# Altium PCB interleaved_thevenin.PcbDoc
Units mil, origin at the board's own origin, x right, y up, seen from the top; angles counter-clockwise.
Board outline 3900.03 x 2830.03 mil, 2 copper layers (Top Layer, Bottom Layer); 43 components, 29 nets, 149 pads, 13 vias.
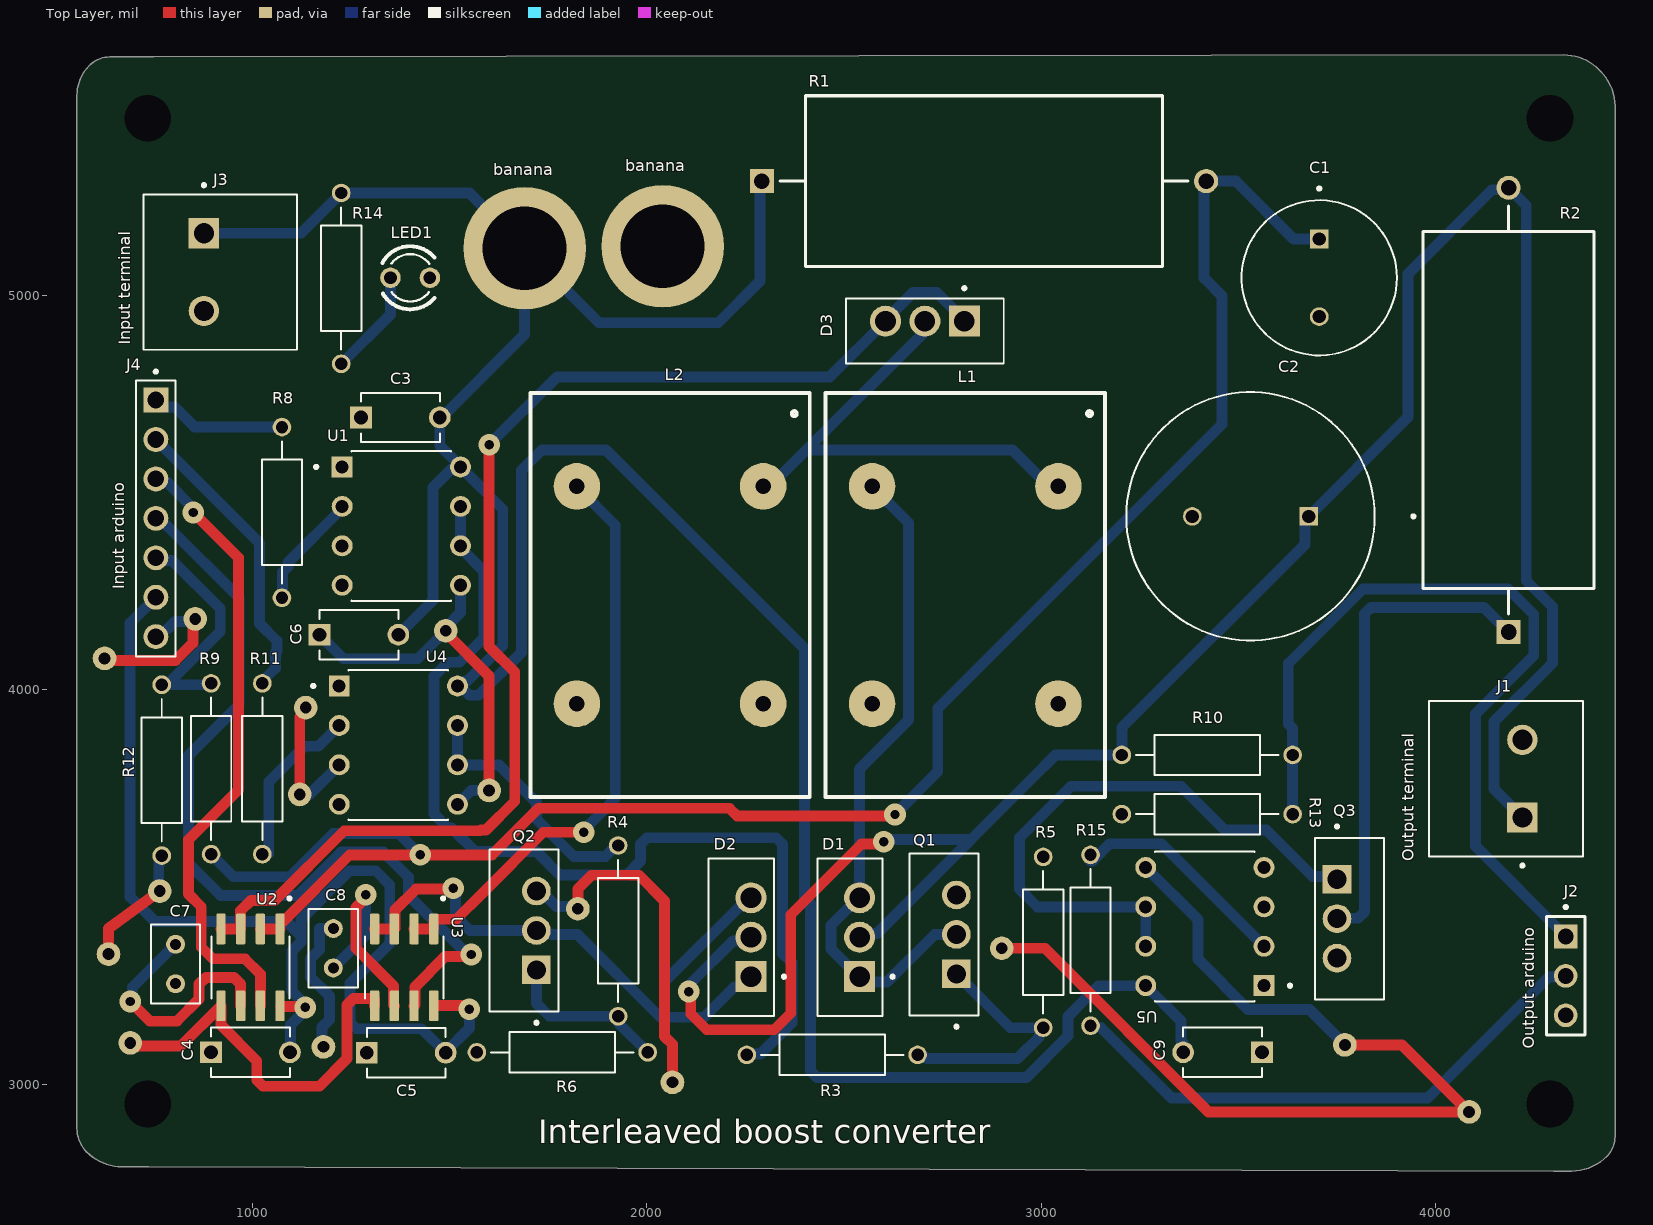
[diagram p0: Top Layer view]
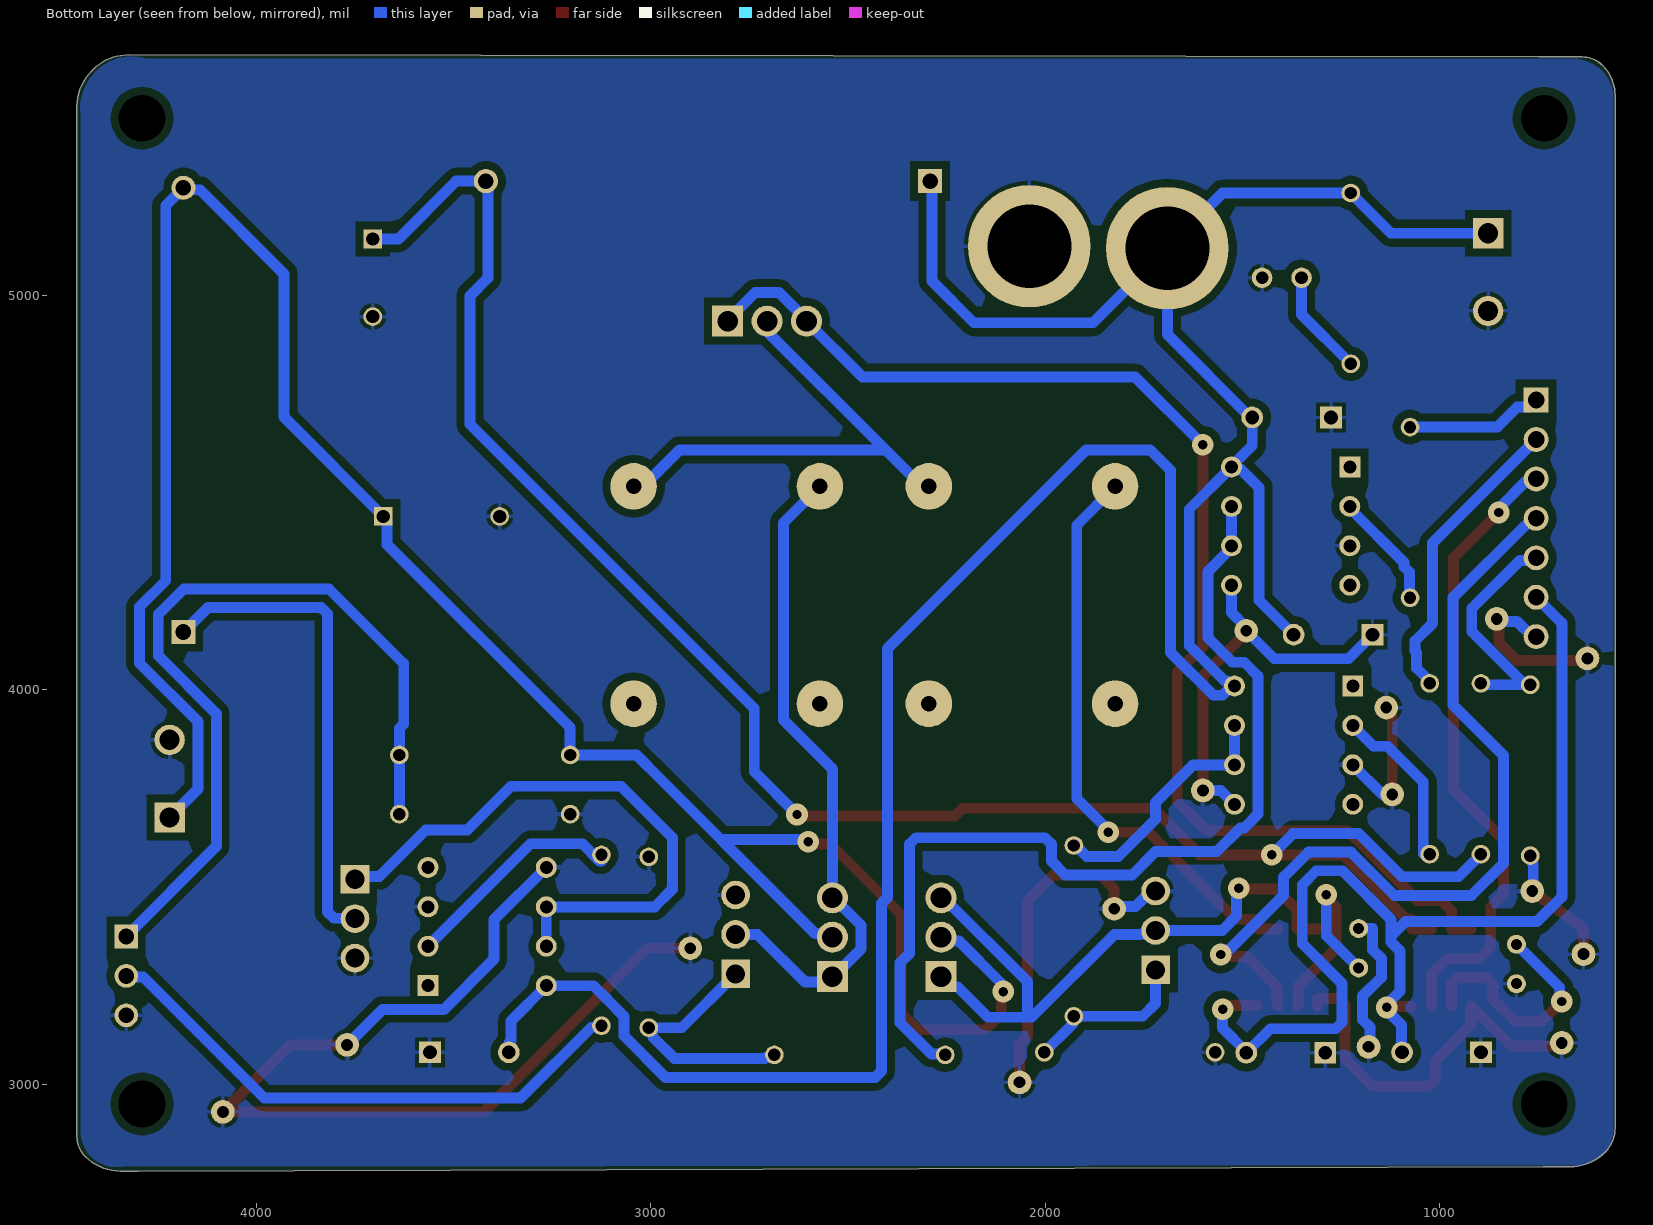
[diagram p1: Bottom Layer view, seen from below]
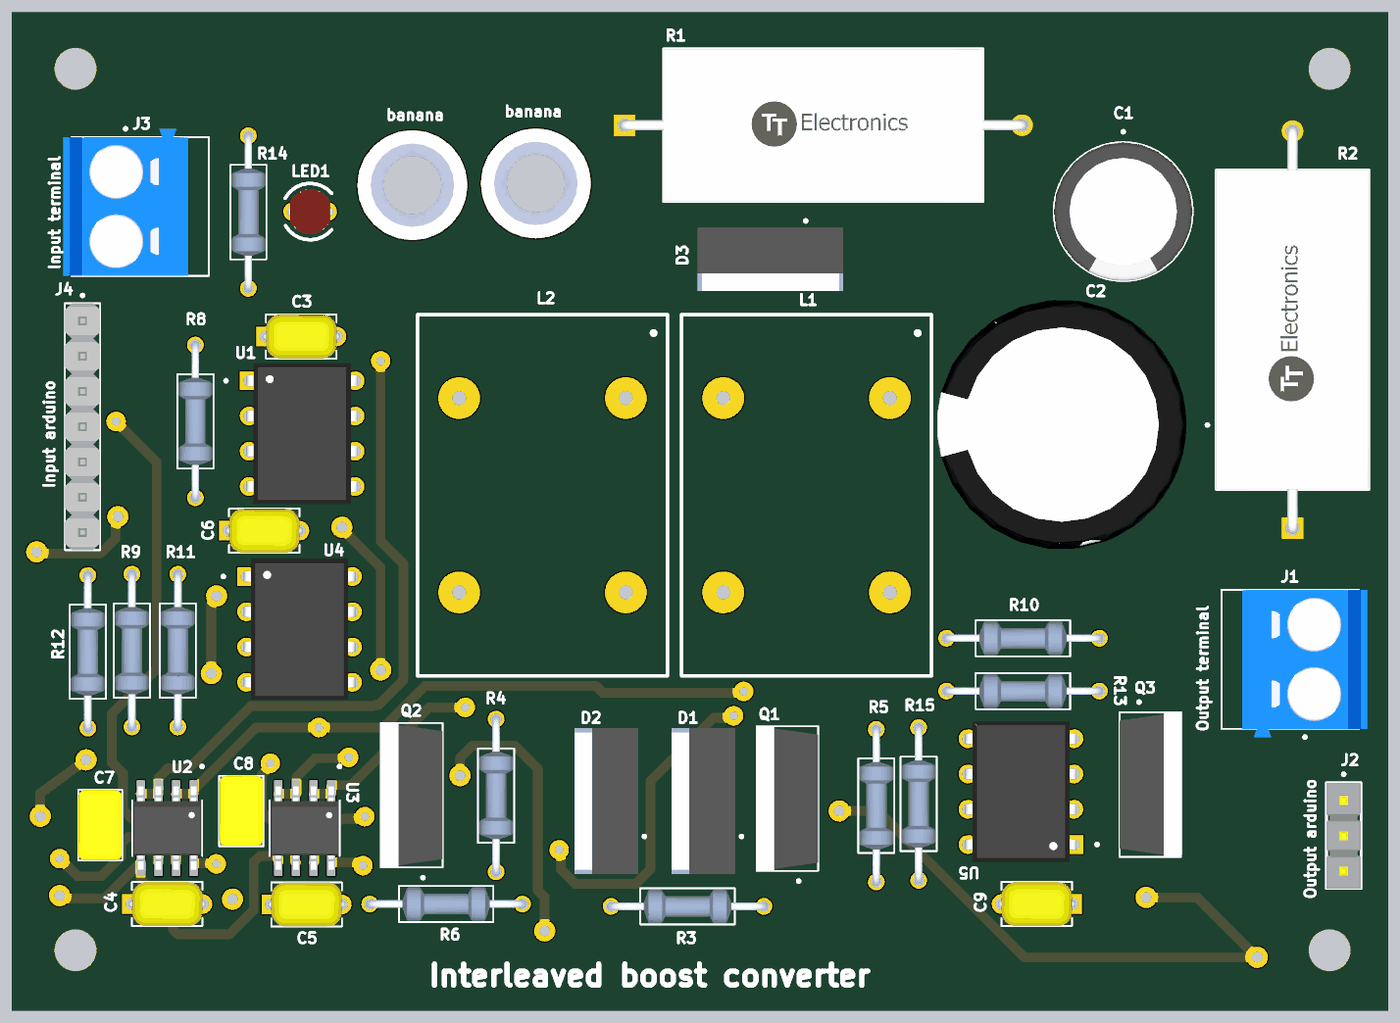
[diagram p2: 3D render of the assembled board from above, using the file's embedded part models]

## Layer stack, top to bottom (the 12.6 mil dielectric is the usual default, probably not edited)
Top Solder: solder mask 0.4, Solder Resist, Dk 3.5
Top Layer: signal copper 1.4
Dielectric 1: dielectric 12.6, FR-4, Dk 4.8
Bottom Layer: signal copper 1.4
Bottom Solder: solder mask 0.4, Solder Resist, Dk 3.5

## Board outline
580.05,2827.86 cw(c640.56,2888.37) 554.99,2888.37 554.99,2910 554.98,5456.69 554.98,5507.57 cw(c662.43,5507.57) 586.45,5583.55 cw(c638.3,5531.7) 638.3,5605.02 749.99,5605.02 4324.99,5610.02 cw(c4325,5484.28) 4413.9,5573.19 4418.19,5568.9 cw(c4329.29,5480) 4455.02,5480 4455.01,2950 4455.01,2867.78 cw(c4382.93,2867.78) 4433.9,2816.81 cw(c4345,2905.71) 4345,2779.99 4299.98,2779.99 736.48,2791.03 725,2791.03 690,2791.03 668.95,2791.03 cw(c668.95,2916.76)

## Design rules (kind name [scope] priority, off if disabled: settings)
Clearance [All] p1: gap=19.68 ignorepadtopadclearanceinfootprint=FALSE
HoleSize [All] p1: absolutevalues=TRUE maxlimit=300 minlimit=1 maxpercent=80.000 minpercent=20.000
PolygonConnect [All] p1: connectstyle=Relief reliefconductorwidth=10 reliefentries=4 polygonreliefangle="90 Angle" airgapwidth=10
RoutingVias [All] p1: holewidth=23.62 width=55.12 viastyle="Through Hole" minholewidth=23.62 minwidth=55.12 maxholewidth=39.37 maxwidth=78.74
SilkToSolderMaskClearance [IsPad] p1: minsilkscreentomaskgap=6 clearancetoexposedcopper=TRUE
SolderMaskExpansion [All] p1: expansion=4 istentingtop=FALSE
SupplyNets "Schematic Supply Nets_2" [InNet('+12')] p1: voltage=0.000
SupplyNets "Schematic Supply Nets_1" [InNet('GND')] p2: voltage=0.000
SupplyNets "Schematic Supply Nets" [InNet('+5')] p3: voltage=0.000
Width [All] p1: maxlimit=393.7 minlimit=27.56 preferedwidth=27.56 minimp=50.000000 maximp=50.000000 favimp=50.000000
28 further rules are at their usual default settings.

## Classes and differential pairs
component class Sheet1: C1 C2 C3 C4 C5 C6 C7 C8 C9 D1 D2 J1 J2 J3 J4 L1 L2 LED1 Q1 Q2 Q3 R1 R2 R3 R4 R5 R6 R8 R9 R10 R11 R12 R13 R14 R15 U1 U2 U3 U4 U5

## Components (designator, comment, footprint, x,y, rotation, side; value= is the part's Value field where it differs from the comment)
1 "Banana con" KEYSTONE_575-4 2040,5125 r90 top
C1 "470uF" 470uF 3705,5045 r270 top
C2 "2200uF cap" "2200uF cap" 3530.65,4440 r180 top
C3 "ceramic cap 100nF" "ceramic cap 100nF" 1375,4690.81 r0 top
C4 "ceramic cap 100nF" "ceramic cap 100nF" 995,3081.1 r0 top
C5 "ceramic cap 100nF" "ceramic cap 100nF" 1390,3080 r0 top
C6 "ceramic cap 100nF" "ceramic cap 100nF" 1270,4140 r0 top
C7 "1nF ceramic cap" "1nF ceramic cap" 805,3305 r270 top
C8 "1nF ceramic cap" "1nF ceramic cap" 1205,3345 r90 top
C9 "ceramic cap 100nF" "ceramic cap 100nF" 3460,3081.1 r180 top
D1 "MBR20100CT" TO254P1066X482X2286-3 2514.88,3372.89 r90 top
D2 "MBR20100CT" TO254P1066X482X2286-3 2239.4,3372.89 r90 top
D3 "MBR20100CT" TO254P1066X482X2286-3 2705,4910.31 r180 top
J1 "output" "terminal block" 4220,3775 r90 top
J2 "output arduino" "3 male pins header" 4330,3275 r90 top
J3 "input power" "terminal block" 876.8,5059.36 r270 top
J4 "input arduino" "7 male pin header" 755,4435 r270 top
L1 "WE-HIDA_1715" "2mH inductor" 2807.45,4240.59 r270 top
L2 "WE-HIDA_1715" "2mH inductor" 2058.78,4240.59 r270 top
LED1 "Red LED" "Red LED" 1400,5045 r0 top
Q1 "IRF540NPBF" TO254P1054X469X1930-3 2753.09,3380 r90 top
Q2 "IRF540NPBF" TO254P1054X469X1930-3 1688.09,3390 r90 top
Q3 "IRF540NPBF" TO254P1054X469X1930-3 3781.91,3420 r270 top
R1 "6.8ohm" "5W power resistor" 2855,5290 r0 top
R2 "47ohm" "5W power resistor" 4185,4710 r90 top
R3 "22ohm" "TH resistor" 2470,3074.58 r0 top
R4 "22ohm" "TH resistor" 1927.25,3388.95 r270 top
R5 "10k ohm" "TH resistor" 3005,3360 r270 top
R6 "10kohm" "TH resistor" 1785.69,3081.1 r0 top
R8 "330 ohm" "TH resistor" 1074.82,4450 r270 top
R9 "10kohm" "TH resistor" 895,3800 r270 top
R10 "330kohm" "TH resistor" 3420.95,3835 r180 top
R11 "330 ohm" "TH resistor" 1025,3800 r270 top
R12 "1kohm" "TH resistor" 770,3796.54 r90 top
R13 "65kohm" "TH resistor" 3420.95,3685 r0 top
R14 "560ohm" "TH resistor" 1225,5043.46 r90 top
R15 "330 ohm" "TH resistor" 3125,3365 r90 top
U1 "TLP250" DIP762W50P254L966H485Q8 1377.47,4415.4 r0 top
U2 "ACS712" ACS712 995,3296.34 r270 top
U3 "ACS712" ACS712 1384.81,3296.34 r270 top
U4 "TLP250" DIP762W50P254L966H485Q8 1370,3860 r0 top
U5 "TLP250" DIP762W50P254L966H485Q8 3415,3400 r180 top
? "Banana con" KEYSTONE_575-4 1690,5120 r0 top

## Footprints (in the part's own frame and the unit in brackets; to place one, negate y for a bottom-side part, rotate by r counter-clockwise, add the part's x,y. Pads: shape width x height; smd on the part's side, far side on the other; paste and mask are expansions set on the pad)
"1nF ceramic cap" [mm]
  round 1.218 hole 0.71: 1(-1.27,0) 2(1.27,0)
  silkscreen extent -2.54,-1.59 2.54,1.59, body extent -2.54,-1.59 2.54,1.59, height 5.08
"2mH inductor" [mm]
  round 3 hole 1: 1(-7,6) 2(-7,-6) 3(7,-6) 4(7,6)
  silkscreen extent -13,-9 13,9
"3 male pins header" [mm]
  rect 1.53x1.53 / inner round 1.53 / far side rect 1.53x1.53 hole 1.02: 01(2.54,0)
  round 1.53 hole 1.02: 02(0,0) 03(-2.54,0)
  silkscreen extent -3.81,-1.24 4.53,1.24, body extent -3.81,-1.24 3.81,1.24, height 8.38
"5W power resistor" [mm]
  rect 1.55x1.55 hole 1 paste-2539.97 mask+0: 1(-14.305,0)
  round 1.55 hole 1 paste-2539.97 mask+0: 2(14.305,0)
  silkscreen extent -13.13,-5.5 13.13,5.5, body extent -15.18,-5.6 15.18,5.6, height 0.25
"7 male pin header" [mm]
  rect 1.605x1.605 / inner round 1.605 / far side rect 1.605x1.605 hole 1.07: 1(-7.62,0)
  round 1.605 hole 1.07: 2(-5.08,0) 3(-2.54,0) 4(0,0) 5(2.54,0) 6(5.08,0) 7(7.62,0)
  silkscreen extent -9.55,-1.27 8.89,1.27, body extent -8.89,-1.27 8.89,1.27, height 8.34
470uF [mm]
  round 1.2 hole 0.85: N(2.5,0)
  rect 1.2x1.2 hole 0.85: P(-2.5,0)
  silkscreen extent -5.85,-5 5,5, body extent -5,-5 5,5, height 12.5
"2200uF cap" [mm]
  round 1.2 hole 0.85: N(3.75,0)
  rect 1.2x1.2 hole 0.85: P(-3.75,0)
  silkscreen extent -10.59,-8 8,8, body extent -8.99,-9.02 8.99,8.97, height 3
ACS712 [mm]
  rrect25% 1.97x0.6 smd paste+0 mask+0.102: 1(-2.475,1.905) 2(-2.475,0.635) 3(-2.475,-0.635) 4(-2.475,-1.905) 5(2.475,-1.905) 6(2.475,-0.635) 7(2.475,0.635) 8(2.475,1.905)
  silkscreen extent -4.54,-2.52 2,2.6, body extent -3,-2.45 3,2.45, height 1.75
"ceramic cap 100nF" [mm]
  rect 1.398x1.398 / inner round 1.398 / far side rect 1.398x1.398 hole 0.89: 1(-2.54,0)
  round 1.398 hole 0.89: 2(2.54,0)
  silkscreen extent -2.54,-1.59 2.54,1.59, body extent -2.79,-1.59 2.79,1.59, height 5.86
DIP762W50P254L966H485Q8 [mm]
  rect 1.348x1.348 / inner round 1.348 / far side rect 1.348x1.348 hole 0.84: 1(-3.81,3.81)
  round 1.348 hole 0.84: 2(-3.81,1.27) 3(-3.81,-1.27) 4(-3.81,-3.81) 5(3.81,-3.81) 6(3.81,-1.27) 7(3.81,1.27) 8(3.81,3.81)
  silkscreen extent -5.58,-4.83 3.2,4.83, body extent -4.02,-5.09 4.02,5.09, height 4.51
KEYSTONE_575-4 [mm]
  round 7.9 hole 5.4: 1(0,0)
  body extent -3.96,-3.96 3.96,3.96, height 2.36
"Red LED" [mil]
  round 52 hole 32: A(-50,0) K(50,0)
  silkscreen extent -71,-80 61,80, body extent -60,-62 60,62, height 240
"terminal block" [mm]
  rect 1.95x1.95 / inner round 1.95 / far side rect 1.95x1.95 hole 1.3: 1(-2.5,0)
  round 1.95 hole 1.3: 2(2.5,0)
  silkscreen extent -5.7,-3.9 5,6, body extent -5.6,-4.5 5,4.5, height 12.6
"TH resistor" [mm]
  round 1.2 hole 0.8: 1(-5.5,0) 2(5.5,0)
  silkscreen extent -4.58,-1.3 4.58,1.3, body extent -5.77,-1.2 5.77,1.2, height 2.4
TO254P1054X469X1930-3 [mm]
  rect 1.845x1.845 / inner round 1.845 / far side rect 1.845x1.845 hole 1.23: 1(-2.54,-0.81)
  round 1.845 hole 1.23: 2(0,-0.81) 3(2.54,-0.81)
  silkscreen extent -6.04,-2.22 5.21,2.22, body extent -5.21,-2.22 5.21,2.22, height 19.3
TO254P1066X482X2286-3 [mm]
  rect 2x2 / inner round 2 / far side rect 2x2 hole 1.33: 1(-2.54,-0.627)
  round 2 hole 1.33: 2(0,-0.627) 3(2.54,-0.627)
  silkscreen extent -5.08,-2.85 5.08,2.09, body extent -5.25,-2.29 5.25,2.3, height 20.2

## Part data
1 ?: "Battery Holders, Contacts and Clips JACK", Package=None
C1: "470ÂµF 25V Aluminum Electrolytic Capacitors Radial, Can 2000 Hrs @ 105Â°C", Package="RADIAL-2 Panasonic"
C2: "CAP ALUM 2200UF 20% 35V RADIAL", Package="RADIAL-2 Panasonic"
C3 C4 C5 C6 C9: "AR 100nF Ceramic Multilayer Cap,50V dc,+125C,X7R Dielectric,+/-10%,Through Hole", Package="Radial AVX"
C7 C8: "SR Series 5.08 x 5.08 mm 1 nF 100 V Â±5% Tolerance C0G/NP0 Radial Lead/SkyCapÂ®", Package="Radial AVX / Kyocera"
D1 D2 D3: "20A, 100V, Planar Schottky", Package="TO-220AB-3 Taiwan Semiconductor"
J1 J3: library part "terminal block", Package=None
J2: library part "3 male pins header", Package=None
J4: library part "7 male pin header", Package=None
L1 L2: library part "2mH E shape"
LED1: "Red 619nm LED Indication - Discrete 1.9V Radial", Package=None
Q1 Q2 Q3: "RoHS Compliant", Package="TO-220 Infineon"
R1 R2: library part "5W power resistor", "CAW54R70JLF Thick Film Resistors - Through Hole 4.7 OHM 5% 5W", Ambient Temperature Range High=155°C, Case/Package=Axial, Power Rating=5W, Resistance=4.7Ω, Temperature Coefficient=400ppm/°C, Tolerance=5%, Voltage Rating=350V
R3 R4 R5 R6 R8 R9 R10 R11 R12 R13 R14 R15: library part "TH resistor", "1.07 kOhms Â±1% 0.25W, 1/4W Through Hole Resistor Axial - Metal Film", Package="RADIAL-2 YAGEO"
U1 U4 U5: "Logic Output Optoisolator - Push-Pull, Totem Pole 3750Vrms 1 Channel 40kV/Âµs CMTI 8-SMD", Package="DIP-8 Toshiba"
U2 U3: "Fully Integrated, Hall-Effect-Based Linear Current Sensor IC with 2.4 kVRMS Isolation and a Low-Resistance Current Conductor", Package=None

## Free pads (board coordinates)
  round 0 hole 118.11: 2(735,2950) 2(735,5450) 2(4290,2950) 2(4290,5450)
  round 60 hole 30: 5(690,3105) 9(855,4180) 11(625,4080) 12(1490,4150) 16(1135,3955) 18(1120,3735) 21(1825,3445) 22(2065,3005) 23(1180,3095) 24(765,3490) 25(635,3330) 26(4085,2930) 27(3770,3100) 28(2900,3345) GND(1600,3745)

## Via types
v1: diameter 55.12, hole 23.62, Top Layer to Bottom Layer, 13 vias

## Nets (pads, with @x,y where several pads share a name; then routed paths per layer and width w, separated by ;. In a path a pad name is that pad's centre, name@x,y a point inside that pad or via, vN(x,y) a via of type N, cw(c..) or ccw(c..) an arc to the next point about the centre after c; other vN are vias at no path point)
+5: C4.2 C5.2 J4.6 U2.8 U3.8 | length 2888.7
  Top Layer w27.56: U2.8@1071.97,3196.95 1132.02,3196.95 v1(1133.98,3195) ; C4.2 C4.2@1095,3088.53 ; U3.8@1461.78,3199.45 1533.09,3199.45 1542.54,3190 v1(1550,3190)
  Bottom Layer w27.56: J4.6 689.94,4169.94 689.94,3475.06 752.56,3412.44 1086.06,3412.44 1120,3378.5 ; C4.2 1096.39,3082.49 1096.39,3149.96 1137.07,3190.64 v1@1137.07,3198.1 ; v1(1133.98,3195) 1133.98,3202.46 1100.31,3236.12 1100.31,3338.36 1122.76,3360.8 1122.76,3378.5 1122.76,3417.76 1246.33,3541.33 1312.5,3541.33 1348.25,3505.58 1348.25,3357.02 1247.01,3255.77 1247.01,3157.13 1263.15,3140.98 1429.02,3140.98 C5.2 ; C5.2@1490,3082.68 1550,3142.68 v1(1550,3190)
+12: ?.1 C3.2 C6.2 C9.2 J3.1 R1.1 R14.2 U1.8 U4.8 U5.8 | length 7568.4
  Bottom Layer w27.56: J3.1 1122.79,5157.79 R14.2 1550,5260 ?.1 ; C6.2 1457.42,4227.42 1457.42,4513.39 1504.55,4560.52 1521.03,4560.52 1527.47,4566.97 1475,4619.44 C3.2 1479.97,4690.81 1690,4900.83 ?.1 ; U4.8 1526.9,4010 1539.66,4022.76 1544.57,4022.76 1634.71,4112.9 1634.71,4458.16 1532.45,4560.43 U1.8@1527.47,4560.43 ; U4.8@1530,4006.9 1550.6,3986.3 1573.5,3986.3 1681.96,4094.77 1681.96,4556.96 1733.7,4608.7 1896.3,4608.7 2400,4105 2400,3473.61 2415,3458.61 2415,3033.63 2431.14,3017.49 2962.49,3017.49 3067.91,3122.91 3067.91,3172.11 3110,3214.2 3110,3215 3145,3250 U5.8 3354.74,3160.26 3354.74,3110.26 C9.2@3360,3105 ; R1.1 2286.81,5285 2286.81,5036.81 2181.02,4931.02 1878.98,4931.02 ?.1
GND: 1.1 C1.N C2.N C3.1 C4.1 C5.1 C6.1 C7.2 C8.2 C9.1 J1.2 J2.03 J3.2 J4.7 LED1.K pad.5 pad.9 pad.11 pad.12 pad.16 pad.18 pad.21 pad.22 pad.23 pad.24 pad.25 pad.26 pad.27 pad.28 pad.GND Q1.3 Q2.3 Q3.3 R5.1 R6.1 R12.1 R13.1 U1.3 U1.5 U2.5 U3.5 U4.3 U4.5 U5.3 U5.5 | length 6903.1
  Top Layer w27.56: pad.25 635,3395 pad.24 ; pad.11@639.72,4075 805,4075 848.79,4118.79 848.79,4173.79 pad.9 ; pad.5 697.79,3097.21 818.31,3097.21 U2.5 920,3150 1010.71,3059.29 1010.71,3011.14 1026.85,2995 1170,2995 1240,3065 1240,3201.42 1256.14,3217.56 1307.84,3217.56 1309.81,3215.59 U3.5 ; pad.18 1120,3931.22 1135,3946.22 pad.16 ; pad.12 1490,4145.32 1600,4035.32 pad.GND ; pad.21 1825,3495 1860,3530 1980,3530 2045,3465 2045,3121.5 2065,3101.5 pad.22 ; pad.28 3009.2,3345 3424.2,2930 pad.26 3915,3100 pad.27
  Bottom Layer w27.56: J4.7 764.64,4135 803.43,4173.79 848.79,4173.79 pad.9 ; pad.24 762.28,3492.72 762.28,3558.37 766.23,3562.31 766.23,3576.23 R12.1 ; pad.18 1145,3735 U4.3 ; C6.1 1230.98,4079.02 1419.02,4079.02 pad.12 1490,4158.78 1527.47,4196.25 U1.5 ; pad.23 1176.21,3098.79 1176.21,3144.91 1195,3163.7 1195,3223.77 1147.56,3271.21 1147.56,3318.79 1170,3341.23 1170,3395 C8.2 ; U4.5 1554.62,3744.62 1599.62,3744.62 pad.GND ; Q2.3 1732.2,3490 1770.99,3451.21 1818.79,3451.21 pad.21 ; U5.5 3397.24,3417.76 3397.24,3317.36 3524.6,3190 3680,3190 pad.27
hycontrol: J2.02 R15.1 | length 1409.5
  Bottom Layer w27.56: R15.1 3128.77,3144.7 3150.3,3144.7 3330.08,2964.92 3979.92,2964.92 4287.03,3272.03 4327.03,3272.03 J2.02
"i/p voltage": J4.5 R9.1 R12.2 | length 569.5
  Bottom Layer w27.56: J4.5 761.64,4328.36 796.39,4328.36 918.46,4206.29 918.46,4148.46 792.91,4022.91 ; R12.2@779.09,4013.07 891.54,4013.07 R9.1
IP+_1: C1.P R1.2 R9.2 U2.1 U2.2 | length 4677.9
  Top Layer w27.56: U2.2 U2.1 ; U2.1@1071.97,3418.78 1077.88,3412.88 1246.83,3581.83 v1(1425.12,3581.83) 1607.07,3581.83 1725.25,3700 2209.14,3700 2229.14,3680 2625,3680 v1(2629.14,3684.14)
  Bottom Layer w27.56: R9.2 952.09,3526.38 1095.32,3526.38 1204.76,3635.82 1371.13,3635.82 v1(1425.12,3581.83) ; v1(2629.14,3684.14) 2737.76,3792.76 2737.76,3952.54 3458.67,4673.46 3458.67,4999.12 3413.19,5044.61 3413.19,5285 R1.2 3493.46,5290 3640.04,5143.43 C1.P
IP+_2: L2.2 U3.1 U3.2 | length 1494.6
  Top Layer w27.56: U3.2 U3.1 1459.81,3416.46 1461.78,3418.43 1516.9,3418.43 1585.17,3486.7 1737.45,3638.98 v1(1840,3638.98)
  Bottom Layer w27.56: L2.2@1822.56,4515 1920,4417.56 1920,3725 1840,3645 v1(1840,3638.98)
IP-_1: D3.1 D3.3 U2.3 U2.4 | length 3235.5
  Top Layer w27.56: U2.4 U2.3 970,3439.97 996.06,3466.03 1056.03,3466.03 1232.85,3642.85 1577.85,3642.85 1580,3645 1592.29,3645 1665,3717.71 1665,4045 1600.09,4109.91 v1@1600.09,4621.44
  Bottom Layer w27.56: v1(1600.09,4621.45) 1772.11,4793.47 2463.47,4793.47 D3.3 2605,4938 2674.83,5007.83 2735.17,5007.83 2779.41,4963.59 2779.41,4960.59 D3.1
IP-_2: D2.1 D2.3 Q2.2 U3.3 U3.4 | length 1635.8
  Top Layer w27.56: U3.4 U3.3 1361.78,3395.75 1361.78,3441.94 1414.57,3494.73 1506.9,3494.73 v1(1509.29,3497.12)
  Bottom Layer w27.56: v1@1514.56,3497.12 1514.56,3426.5 1551.06,3390 Q2.2 1728.63,3381.37 1757.31,3381.37 1758.68,3380 1824.19,3380 2034.19,3170 2044.95,3170 ; D2.1 2238.49,3247.3 2222.3,3247.3 2145,3170 2044.95,3170 ; D2.3 2257.62,3472.89 2044.95,3260.23 2044.95,3170
MOSFET_1: R3.1 U1.6 U1.7 | length 2505.1
  Bottom Layer w27.56: U1.7 1527.47,4360.43 1587.47,4300.43 1587.47,4132.47 1525,4070 1495.15,4070 1460,4034.85 1460,3685.15 1495.15,3650 1505,3650 1565,3590 1720,3590 1779.29,3530.71 1949.26,3530.71 1984.34,3565.78 1984.34,3608.86 2000.48,3625 2327.94,3625 2344.08,3608.86 2344.08,3331.74 2367.76,3308.07 2367.76,3156.05 2288.25,3076.54 2255.43,3076.54 R3.1
MOSFET_2: R4.1 U4.6 U4.7 | length 639.4
  Bottom Layer w27.56: U4.7 U4.6 1624.75,3810 1720.51,3714.25 1720.51,3672.17 1814.72,3577.95 1894.39,3577.95 1921.92,3605.48 R4.1
NetC7_1: C7.1 U2.6 | length 623.6
  Top Layer w27.56: v1(690,3210) 740,3160 808.19,3160 864.74,3216.55 864.74,3254.04 881.84,3271.15 952.89,3271.15 970,3254.04 U2.6
  Bottom Layer w27.56: v1(690,3210) 695.27,3215.27 695.27,3245.27 C7.1
NetC8_1: C8.1 U3.6 | length 551.3
  Top Layer w27.56: v1(1287.23,3480.31) 1287.23,3472.85 1262.57,3448.19 1262.57,3344.84 1357.84,3249.57 1357.84,3200.87 U3.6
  Bottom Layer w27.56: C8.1 1287.23,3377.23 v1(1287.23,3480.31)
NetD1_1: D1.1 D1.3 L1.2 Q1.2 | length 1698.1
  Bottom Layer w27.56: L1.2 2663.75,4423.66 2663.75,3923.75 2539.56,3799.56 D1.3 2536.56,3472.89 2466.73,3403.06 2466.73,3342.72 2510.97,3298.48 2513.97,3298.48 D1.1 2553.18,3259.27 2609.27,3259.27 2730.15,3380.15 2784.85,3380.15 Q1.2
NetD3_2: D3.2 L1.1 L2.1 | length 1269.7
  Bottom Layer w27.56: L2.1@2295,4515 L2.1@2308.51,4515 ; L2.1@2311.27,4515 2406.92,4610.65 2705,4908.73 D3.2 ; 2408.87,4608.7 2926.97,4608.7 3019.49,4516.18 L1.1
NetLED1_A: LED1.A R14.1 | length 269.8
  Bottom Layer w27.56: R14.1 1350,4951.93 LED1.A
NetQ1_1: Q1.1 R3.2 R5.2 | length 639.4
  Bottom Layer w27.56: R3.2 2690.3,3070.81 2704.22,3070.81 2710.03,3065 2940,3065 2995.16,3120.16 2995.16,3128.3 3005,3138.14 R5.2 2921.54,3143.46 Q1.1
NetQ2_1: Q2.1 R4.2 R6.2 | length 428.1
  Bottom Layer w27.56: Q2.1 1720,3205 1752.59,3172.41 R4.2 1931.02,3168.64 1931.02,3152.3 R6.2
NetQ3_2: Q3.2 R2.1 | length 1230.4
  Bottom Layer w27.56: Q3.2 3751.07,3421.07 3803.64,3421.07 3819.78,3437.21 3819.78,4192.95 3835.93,4209.1 4122.71,4209.1 R2.1
NetR8_2: R8.2 U1.2 | length 295.2
  Bottom Layer w27.56: R8.2 1076.22,4234.86 1076.22,4298.43 1090,4312.21 1090,4322.96 1227.47,4460.43 U1.2
NetR11_2: R11.2 U4.2 | length 422
  Bottom Layer w27.56: R11.2@1040,3583.46 1041.22,3584.68 1041.22,3766.89 1131.57,3857.24 1167.24,3857.24 U4.2
NetR15_2: R15.2 U5.2 | length 565.7
  Bottom Layer w27.56: R15.2@3125,3566.54 3129.94,3566.54 3173.4,3610 3305,3610 U5.2
"o/p voltage": J2.01 R10.1 R13.2 | length 2086.5
  Bottom Layer w27.56: R13.2 3637.48,3902.79 3626.54,3913.74 3626.54,4066.52 3816.36,4256.34 4183.82,4256.34 4248.98,4191.18 4248.98,4087.16 4100.91,3939.09 4100.91,3604.09 J2.01
"output voltage": C2.P D1.2 D2.2 J1.1 R2.2 R10.2 | length 5806.6
  Top Layer w27.56: v1(2106.02,3235) 2111.3,3229.73 2111.3,3178.7 2151.82,3138.18 2323.18,3138.18 2365,3180 2365,3430 2544.73,3609.73 2595.31,3609.73 v1(2600.59,3615)
  Bottom Layer w27.56: v1(2106.02,3235) 2111.3,3240.27 2111.3,3256.3 2218.1,3363.1 2254.29,3363.1 D2.2 ; D1.2 2549.35,3382.69 2583.89,3382.69 2819.52,3618.32 ; v1(2600.59,3615) 2605.86,3620.27 2821.47,3620.27 3005.19,3803.99 ; 3007.14,3805.94 3036.2,3835 R10.2 3204.41,3904.95 3668.45,4368.98 3668.45,4430.16 3930,4691.71 3930,5055 4143.35,5268.35 4180.16,5268.35 R2.2 4230,5228.19 4230,4276.97 4296.22,4210.75 4296.22,4067.59 4148.15,3919.52 4148.15,3748.43 J1.1
PWM_1: J4.1 R8.1 | length 348.2
  Bottom Layer w27.56: J4.1 772.81,4717.19 802.81,4717.19 853.46,4666.54 R8.1
PWM_2: J4.2 R11.1 | length 760.8
  Bottom Layer w27.56: J4.2 1017.74,4372.26 1017.74,4168.8 1061.77,4124.76 1061.77,4098.75 1057.96,4094.94 1057.96,4054.82 1025,4021.86 R11.1
storage_mosfet: Q3.1 U5.6 U5.7 | length 1525.4
  Bottom Layer w27.56: U5.7 U5.6 2990,3450 2945,3495 2945,3625 3075.68,3755.68 3354.31,3755.68 3465.48,3644.51 3570.49,3644.51 3688.49,3526.51 3743.49,3526.51 Q3.1
Vout_1: J4.3 U2.7 | length 1610.6
  Top Layer w27.56: v1(850,4450) 965,4335 965,3747.01 837.91,3619.92 837.91,3482.09 870,3450 870,3347.6 899.21,3318.39 980.63,3318.39 1020,3279.02 U2.7
  Bottom Layer w27.56: J4.3 761.82,4528.18 781.82,4528.18 850,4460 v1(850,4450)
Vout_2: J4.4 U3.7 | length 2177.9
  Top Layer w27.56: U3.7 1411.78,3200.87 1411.78,3247.06 1488.43,3323.7 1549.73,3323.7 v1(1555,3328.98)
  Bottom Layer w27.56: J4.4 764.64,4435 782.46,4417.19 782.81,4417.19 965.71,4234.29 965.71,3961.86 837.91,3834.06 837.91,3559.82 918.6,3479.13 1114.89,3479.13 1224.33,3588.57 1332.07,3588.57 1395.49,3525.15 1395.49,3478.75 1531.49,3342.76 1533.76,3342.76 1547.54,3328.98 v1(1555,3328.98)
pads on no net: L1.3 L1.4 L2.3 L2.4 U1.1 U1.4 U4.1 U4.4 U5.1 U5.4

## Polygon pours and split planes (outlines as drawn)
GND on Bottom Layer "GND_L02_P000" (solid, remove dead copper, pour order 0): 4275.82,5600 cw(c4315.08,5474.66) 4445,5455.36 4445,2878.27 cw(c4354.76,2880.08) 4340,2791.03 664.99,2794.99 cw(c651.3,2885.26) 560,2885 560,5500.01 cw(c660,5500.01) 658.8,5600

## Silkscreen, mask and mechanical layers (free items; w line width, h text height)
Top Overlay:
  text "Input terminal" at 690,4875 h30 r90
  text "Input arduino" at 675,4255 h30 r90
  text "Output terminal" at 3945,3565 h30 r90
  text "Output arduino" at 4250,3090 h30 r90
  text "Interleaved boost converter" at 1725,2850 h60
Mechanical 1:
  lines w10: 560,2892.43 ccw(c662.43,2892.43) 590,2820 ccw(c647.82,2877.82) 647.82,2796.05 736.5,2796.05 4300,2785 4345,2785 ccw(c4345,2905.71) 4430.36,2820.36 ccw(c4382.93,2867.78) 4450,2867.78 4450,2950 4450,5480 ccw(c4329.29,5480) 4414.64,5565.36 4410.36,5569.64 ccw(c4325,5484.29) 4325,5605 749.99,5600.01 638.3,5600.01 ccw(c638.3,5531.7) 590,5580 ccw(c662.43,5507.57) 560,5507.57 560,5456.69 560,2910 560,2892.43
